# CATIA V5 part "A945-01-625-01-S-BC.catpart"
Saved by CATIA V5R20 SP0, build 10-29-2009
Part number: A945-01-620-01-S-BC
Source: Unknown
Property "ARTICLENO": "A945-01-620-01-S-BC"
Property "B": "65.000"
Property "BOMINFO": "A945-01-620-01-S-BC"
Property "CODE": "A945-01-620-01-S-BC"
Property "D1": "20.000"
Property "D2": "13.500"
Property "D5": "16.000"
Property "D6": "12.000"
Property "H": "47.000"
Property "H1": "34.000"
Property "H2": "35.000"
Property "H3": "18.000"
Property "L1": "250.000"
Property "L2": "25.000"
Property "L3": "100.000"
Property "L4": "100.000"
Property "L5": "55.000"
Property "L6": "145.000"
Property "LINA": "A945-01-620-01-S-BC"
Property "N": "3.000"
Property "NB": "A945-01-620-01-S-BC"
Property "NBSYN": " $CODE."
Property "NN": "A945"
Property "NT": "v driver sets replaceable inserts pisitive return"
Property "SUPPLIER": "CF"
Property "Z": "65.000"
Bounding box of the stored display mesh (mm): x -5049.207 to -4951.207, y -575.36 to -510.36, z 0 to 250
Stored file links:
  C:\Users\Utente\Desktop\3D files A945-01\A945-01-625-01-S-BC.catpart
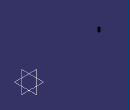
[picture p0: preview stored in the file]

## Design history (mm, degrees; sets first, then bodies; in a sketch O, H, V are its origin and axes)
Body1 "Geometry.1" (main body)
  Solid1 "A945-01-620-01-S-BC.catpart": solid without history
